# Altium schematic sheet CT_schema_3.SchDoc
size 339 x 183 mm
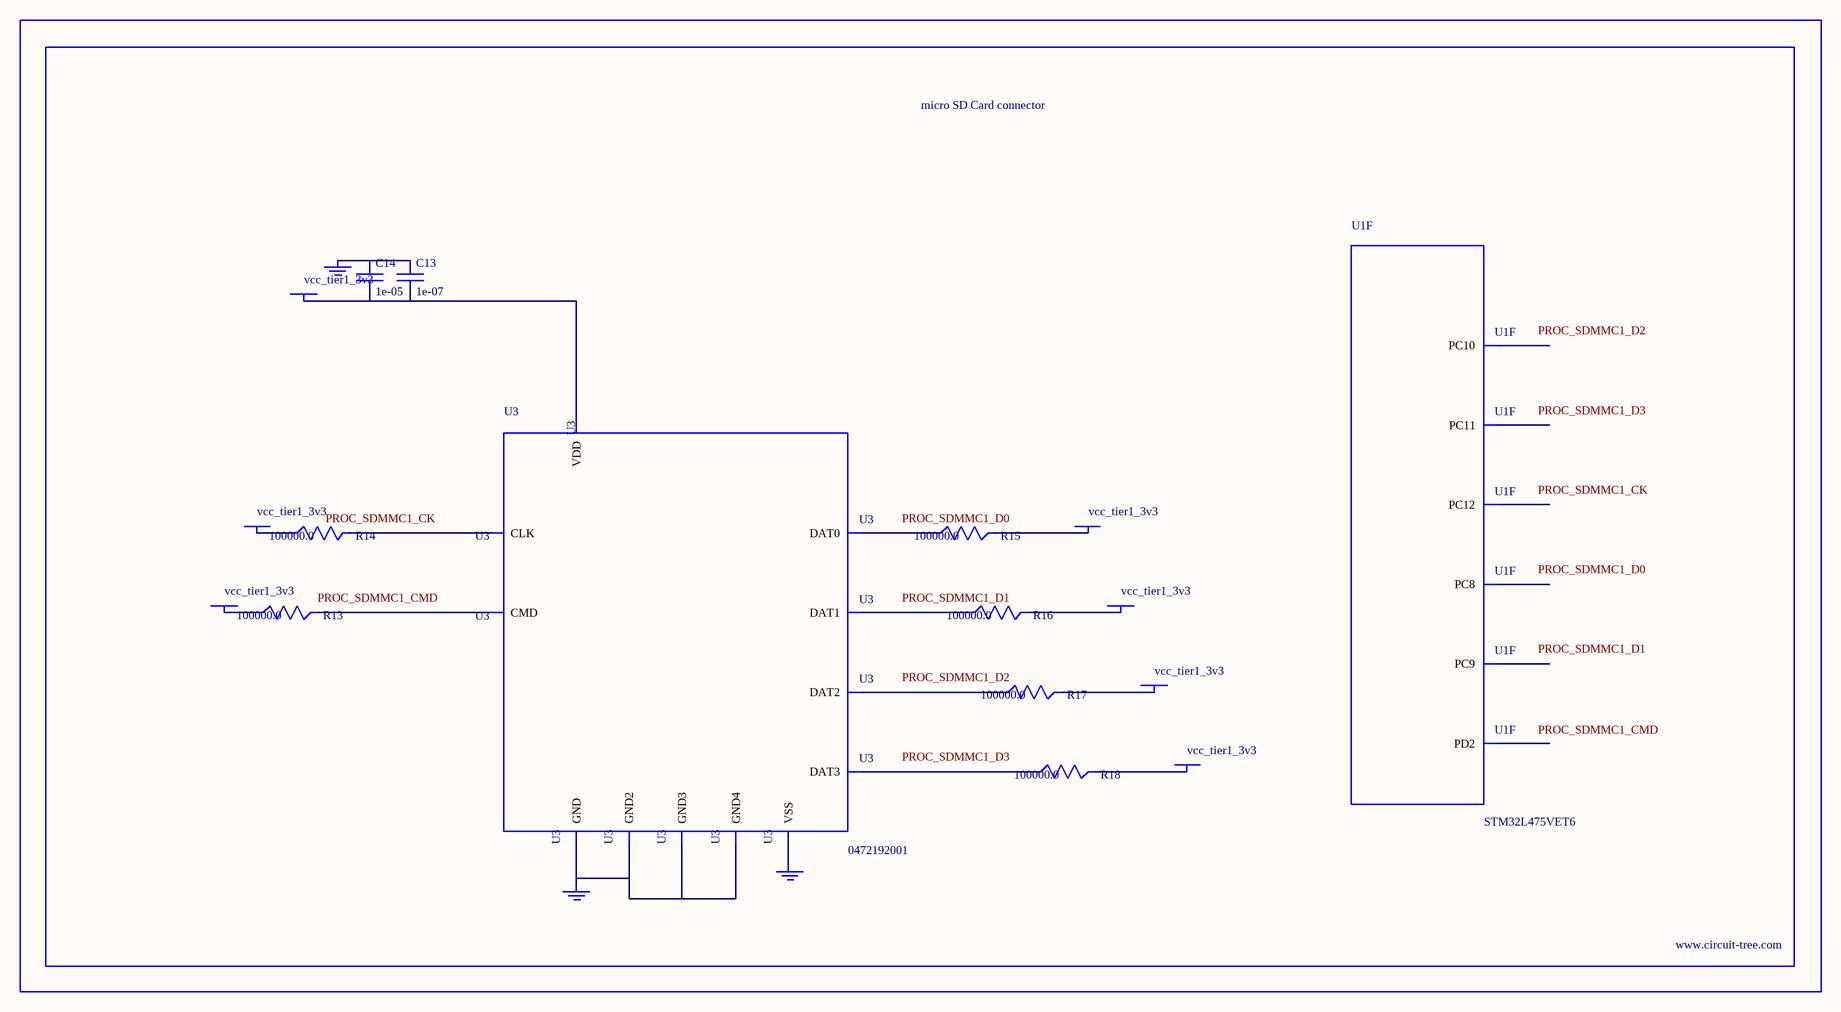
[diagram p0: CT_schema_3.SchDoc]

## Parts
BORDER2  (no value)
C13  1e-07  [C0402]
C14  1e-05  [C0805]
GND_INSTANCE_2_0  (no value)
GND_INSTANCE_2_1  (no value)
GND_INSTANCE_2_2  (no value)
POWER_INSTANCE_2_0  vcc_tier1_3v3
POWER_INSTANCE_2_1  vcc_tier1_3v3
POWER_INSTANCE_2_2  vcc_tier1_3v3
POWER_INSTANCE_2_3  vcc_tier1_3v3
POWER_INSTANCE_2_4  vcc_tier1_3v3
POWER_INSTANCE_2_5  vcc_tier1_3v3
POWER_INSTANCE_2_6  vcc_tier1_3v3
R13  100000.0  [R0603]
R14  100000.0  [R0603]
R15  100000.0  [R0603]
R16  100000.0  [R0603]
R17  100000.0  [R0603]
R18  100000.0  [R0603]
U1  STM32L475VET6  [LQFP100]  (part F of 9)
U3  0472192001  [MOLEX_47219-2001]

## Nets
NetC13_1: C13.1 C14.1 GND_INSTANCE_2_0.0(GND)
NetC13_2: C13.2 C14.2 POWER_INSTANCE_2_3.0(PWR) U3.4(VDD)
NetGND_INSTANCE_2_1_0: GND_INSTANCE_2_1.0(GND) U3.6(VSS)
NetGND_INSTANCE_2_2_0: GND_INSTANCE_2_2.0(GND) U3.G1(GND) U3.G2(GND2) U3.G3(GND3) U3.G4(GND4)
NetPOWER_INSTANCE_2_0_0: POWER_INSTANCE_2_0.0(PWR) R17.2
NetPOWER_INSTANCE_2_1_0: POWER_INSTANCE_2_1.0(PWR) R18.2
NetPOWER_INSTANCE_2_2_0: POWER_INSTANCE_2_2.0(PWR) R13.1
NetPOWER_INSTANCE_2_4_0: POWER_INSTANCE_2_4.0(PWR) R14.1
NetPOWER_INSTANCE_2_5_0: POWER_INSTANCE_2_5.0(PWR) R15.2
NetPOWER_INSTANCE_2_6_0: POWER_INSTANCE_2_6.0(PWR) R16.2
NetR13_2: R13.2 U3.3(CMD)
NetR14_2: R14.2 U3.5(CLK)
NetR15_1: R15.1 U3.7(DAT0)
NetR16_1: R16.1 U3.8(DAT1)
NetR17_1: R17.1 U3.1(DAT2)
NetR18_1: R18.1 U3.2(DAT3)

Not connected (* = marked no-connect by the designer): U1 65(PC8) 66(PC9) 78(PC10) 79(PC11) 80(PC12) 83(PD2)

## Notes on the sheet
- Labels drawn without touching a wire or pin: PROC_SDMMC1_CK, PROC_SDMMC1_CMD, PROC_SDMMC1_D0, PROC_SDMMC1_D1, PROC_SDMMC1_D2, PROC_SDMMC1_D3

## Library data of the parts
BORDER2 = BORDER_PAGE2
C13 = C0402C104K3RACTU
C14 = C0805C106K8RACTU
GND_INSTANCE_2_0-GND_INSTANCE_2_2 = GND
POWER_INSTANCE_2_0-POWER_INSTANCE_2_6 = PWR
R13-R18 = RC0603JR-07100KL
